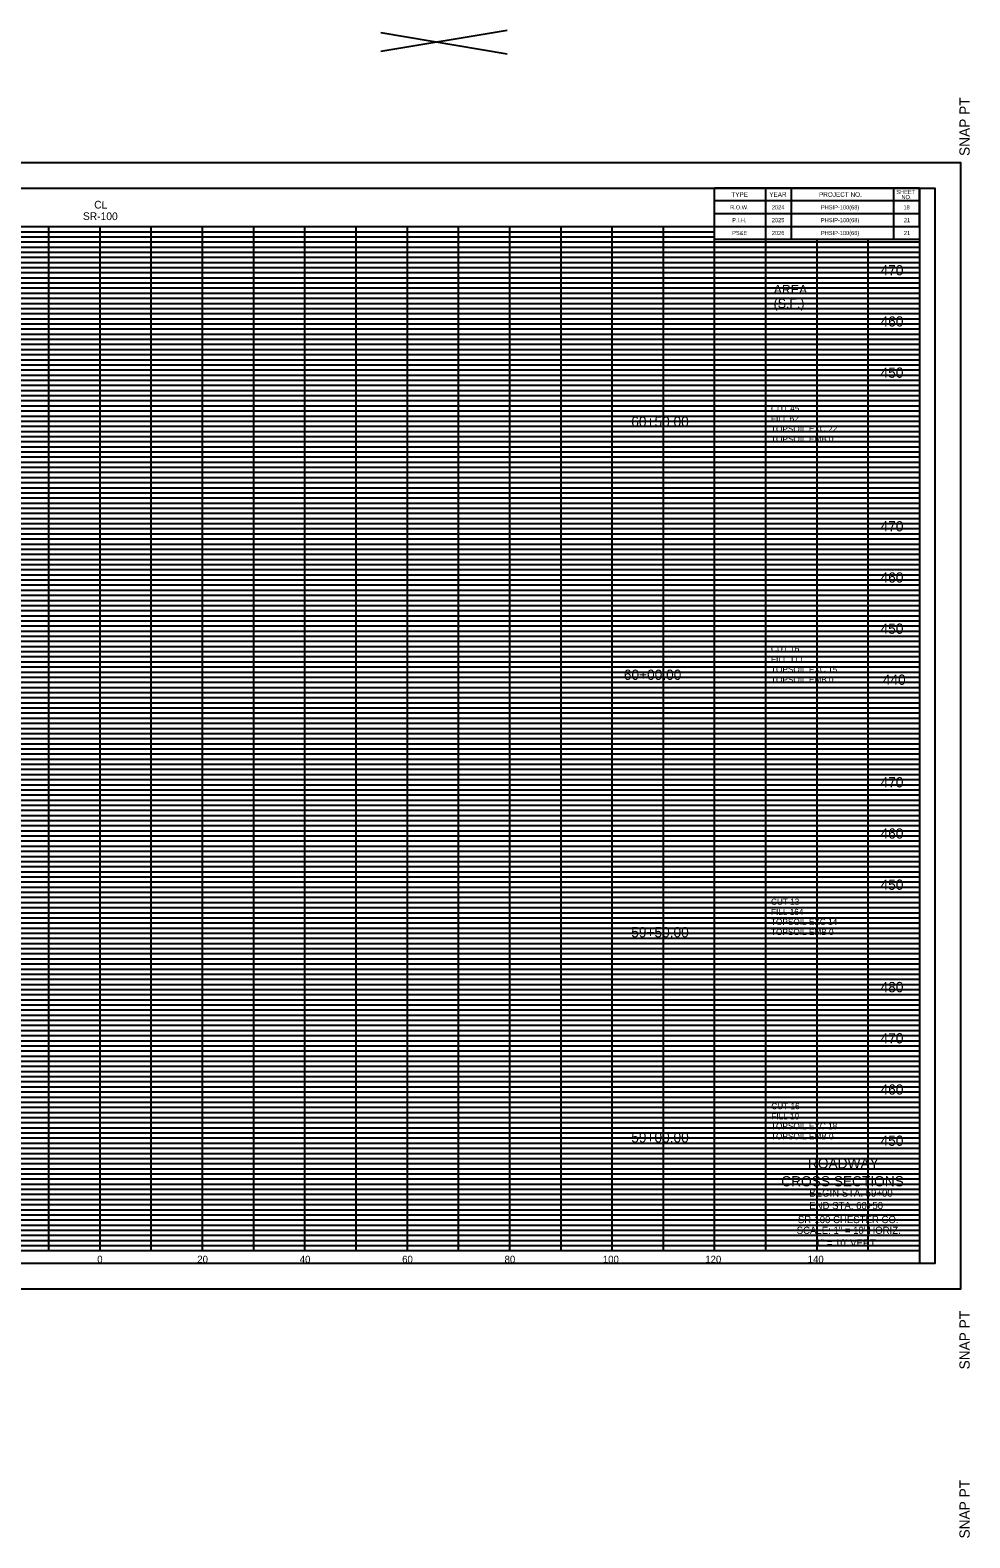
# Model space of a CAD drawing. Extents: x 37 to 1710, y 707 to 2305.
# Drawn here: x 1146.3 to 1329.8, y 1213.9 to 1508.4 of the extents above; entities that cross this region are included whole.
import ezdxf

# ---------------------------------------------------------------- set-up
doc = ezdxf.new("R2010")
doc.units = 0
for name, color, linetype in [('DESIGN - DRAINAGE - Special Ditch Width Text', 7, 'Continuous'), ('DESIGN - SCRATCH - User 1', 7, 'Continuous'), ('DESIGN - SHEET - Corner Text', 7, 'Continuous'), ('DESIGN - SHEET - Light Grid', 7, 'Continuous'), ('DESIGN - SHEET - Linework', 7, 'Continuous'), ('DESIGN - SHEET - Plot Shape', 7, 'Continuous'), ('DESIGN - TYPICAL - Text', 7, 'Continuous')]:
    doc.layers.add(name, color=color, linetype=linetype)

msp = doc.modelspace()

# ---------------------------------------------------------------- linework, layer by layer
at = {"layer": 'DESIGN - SCRATCH - User 1'}
for p, q in [((1214.81, 1504.24), (1239.5, 1508.36)), ((1214.81, 1507.87), (1239.5, 1503.75)), ((1285, 1473.75), (1285, 1473.75)), ((1292.5, 1473.75), (1292.5, 1473.75)), ((1305, 1473.75), (1305, 1473.75)), ((1317.5, 1473.75), (1317.5, 1473.75)), ((1285, 1471.25), (1285, 1471.25)), ((1292.5, 1471.25), (1292.5, 1471.25)), ((1305, 1471.25), (1305, 1471.25)), ((1317.5, 1471.25), (1317.5, 1471.25))]:
    msp.add_line(p, q, dxfattribs=at)
at = {"layer": 'DESIGN - SHEET - Light Grid'}
for p, q in [((1000, 1469), (1280, 1469)), ((1000, 1468), (1280, 1468)), ((1000, 1467), (1320, 1467)), ((1000, 1466), (1320, 1466)), ((1000, 1465), (1320, 1465)), ((1000, 1464), (1320, 1464)), ((1000, 1463), (1320, 1463)), ((1000, 1462), (1320, 1462)), ((1000, 1461), (1320, 1461)), ((1000, 1459), (1320, 1459)), ((1000, 1458), (1320, 1458)), ((1000, 1457), (1320, 1457)), ((1000, 1456), (1320, 1456)), ((1000, 1455), (1320, 1455)), ((1000, 1454), (1320, 1454)), ((1000, 1453), (1320, 1453)), ((1000, 1452), (1320, 1452)), ((1000, 1451), (1320, 1451)), ((1000, 1449), (1320, 1449)), ((1000, 1448), (1320, 1448)), ((1000, 1447), (1320, 1447)), ((1000, 1446), (1320, 1446)), ((1000, 1445), (1320, 1445)), ((1000, 1444), (1320, 1444)), ((1000, 1443), (1320, 1443)), ((1000, 1442), (1320, 1442)), ((1000, 1441), (1320, 1441)), ((1000, 1439), (1320, 1439)), ((1000, 1438), (1320, 1438)), ((1000, 1437), (1320, 1437)), ((1000, 1436), (1320, 1436)), ((1000, 1435), (1320, 1435)), ((1000, 1434), (1320, 1434)), ((1000, 1433), (1320, 1433)), ((1000, 1432), (1320, 1432)), ((1000, 1431), (1320, 1431)), ((1000, 1429), (1320, 1429)), ((1000, 1428), (1320, 1428)), ((1000, 1427), (1320, 1427)), ((1000, 1426), (1320, 1426)), ((1000, 1425), (1320, 1425)), ((1000, 1424), (1320, 1424)), ((1000, 1423), (1320, 1423)), ((1000, 1422), (1320, 1422)), ((1000, 1421), (1320, 1421)), ((1000, 1419), (1320, 1419)), ((1000, 1418), (1320, 1418)), ((1000, 1417), (1320, 1417)), ((1000, 1416), (1320, 1416)), ((1000, 1415), (1320, 1415)), ((1000, 1414), (1320, 1414)), ((1000, 1413), (1320, 1413)), ((1000, 1412), (1320, 1412)), ((1000, 1411), (1320, 1411)), ((1000, 1409), (1320, 1409)), ((1000, 1408), (1320, 1408)), ((1000, 1407), (1320, 1407)), ((1000, 1406), (1320, 1406)), ((1000, 1405), (1320, 1405)), ((1000, 1404), (1320, 1404)), ((1000, 1403), (1320, 1403)), ((1000, 1402), (1320, 1402)), ((1000, 1401), (1320, 1401)), ((1000, 1399), (1320, 1399)), ((1000, 1398), (1320, 1398)), ((1000, 1397), (1320, 1397)), ((1000, 1396), (1320, 1396)), ((1000, 1395), (1320, 1395)), ((1000, 1394), (1320, 1394)), ((1000, 1393), (1320, 1393)), ((1000, 1392), (1320, 1392)), ((1000, 1391), (1320, 1391)), ((1000, 1389), (1320, 1389)), ((1000, 1388), (1320, 1388)), ((1000, 1387), (1320, 1387)), ((1000, 1386), (1320, 1386)), ((1000, 1385), (1320, 1385)), ((1000, 1384), (1320, 1384)), ((1000, 1383), (1320, 1383)), ((1000, 1382), (1320, 1382)), ((1000, 1381), (1320, 1381)), ((1000, 1379), (1320, 1379)), ((1000, 1378), (1320, 1378)), ((1000, 1377), (1320, 1377)), ((1000, 1376), (1320, 1376)), ((1000, 1375), (1320, 1375)), ((1000, 1374), (1320, 1374)), ((1000, 1373), (1320, 1373)), ((1000, 1372), (1320, 1372)), ((1000, 1371), (1320, 1371)), ((1000, 1369), (1320, 1369)), ((1000, 1368), (1320, 1368)), ((1000, 1367), (1320, 1367)), ((1000, 1366), (1320, 1366)), ((1000, 1365), (1320, 1365)), ((1000, 1364), (1320, 1364)), ((1000, 1363), (1320, 1363)), ((1000, 1362), (1320, 1362)), ((1000, 1361), (1320, 1361)), ((1000, 1359), (1320, 1359)), ((1000, 1358), (1320, 1358)), ((1000, 1357), (1320, 1357)), ((1000, 1356), (1320, 1356)), ((1000, 1355), (1320, 1355)), ((1000, 1354), (1320, 1354)), ((1000, 1353), (1320, 1353)), ((1000, 1352), (1320, 1352)), ((1000, 1351), (1320, 1351)), ((1000, 1349), (1320, 1349)), ((1000, 1348), (1320, 1348)), ((1000, 1347), (1320, 1347)), ((1000, 1346), (1320, 1346)), ((1000, 1345), (1320, 1345)), ((1000, 1344), (1320, 1344)), ((1000, 1343), (1320, 1343)), ((1000, 1342), (1320, 1342)), ((1000, 1341), (1320, 1341)), ((1000, 1339), (1320, 1339)), ((1000, 1338), (1320, 1338)), ((1000, 1337), (1320, 1337)), ((1000, 1336), (1320, 1336)), ((1000, 1335), (1320, 1335)), ((1000, 1334), (1320, 1334)), ((1000, 1333), (1320, 1333)), ((1000, 1332), (1320, 1332)), ((1000, 1331), (1320, 1331)), ((1000, 1329), (1320, 1329)), ((1000, 1328), (1320, 1328)), ((1000, 1327), (1320, 1327)), ((1000, 1326), (1320, 1326)), ((1000, 1325), (1320, 1325)), ((1000, 1324), (1320, 1324)), ((1000, 1323), (1320, 1323)), ((1000, 1322), (1320, 1322)), ((1000, 1321), (1320, 1321)), ((1000, 1319), (1320, 1319)), ((1000, 1318), (1320, 1318)), ((1000, 1317), (1320, 1317)), ((1000, 1316), (1320, 1316)), ((1000, 1315), (1320, 1315)), ((1000, 1314), (1320, 1314)), ((1000, 1313), (1320, 1313)), ((1000, 1312), (1320, 1312)), ((1000, 1311), (1320, 1311)), ((1000, 1309), (1320, 1309)), ((1000, 1308), (1320, 1308)), ((1000, 1307), (1320, 1307)), ((1000, 1306), (1320, 1306)), ((1000, 1305), (1320, 1305)), ((1000, 1304), (1320, 1304)), ((1000, 1303), (1320, 1303)), ((1000, 1302), (1320, 1302)), ((1000, 1301), (1320, 1301)), ((1000, 1299), (1320, 1299)), ((1000, 1298), (1320, 1298)), ((1000, 1297), (1320, 1297)), ((1000, 1296), (1320, 1296)), ((1000, 1295), (1320, 1295)), ((1000, 1294), (1320, 1294)), ((1000, 1293), (1320, 1293)), ((1000, 1292), (1320, 1292)), ((1000, 1291), (1320, 1291)), ((1000, 1289), (1320, 1289)), ((1000, 1288), (1320, 1288)), ((1000, 1287), (1320, 1287)), ((1000, 1286), (1320, 1286)), ((1000, 1285), (1320, 1285)), ((1000, 1284), (1320, 1284)), ((1000, 1283), (1320, 1283)), ((1000, 1282), (1320, 1282)), ((1000, 1281), (1320, 1281)), ((1000, 1279), (1320, 1279)), ((1000, 1278), (1320, 1278)), ((1000, 1277), (1320, 1277)), ((1000, 1276), (1320, 1276)), ((1000, 1275), (1320, 1275)), ((1000, 1274), (1320, 1274)), ((1000, 1273), (1320, 1273)), ((1000, 1272), (1320, 1272)), ((1000, 1271), (1320, 1271))]:
    msp.add_line(p, q, dxfattribs=at)
at = {"layer": 'DESIGN - SHEET - Linework'}
for p, q in [((1320, 1477.5), (1280, 1477.5)), ((1280, 1470), (1280, 1477.5)), ((1290, 1470), (1290, 1477.5)), ((1295, 1467.5), (1295, 1477.5)), ((1315, 1467.5), (1315, 1477.5)), ((1320, 1470), (1320, 1477.5)), ((1320, 1475), (1280, 1475)), ((1320, 1472.5), (1280, 1472.5)), ((1000, 1470), (1320, 1470)), ((1150, 1270), (1150, 1470)), ((1160, 1270), (1160, 1470)), ((1170, 1270), (1170, 1470)), ((1180, 1270), (1180, 1470)), ((1190, 1270), (1190, 1470)), ((1200, 1270), (1200, 1470)), ((1210, 1270), (1210, 1470)), ((1220, 1270), (1220, 1470)), ((1230, 1270), (1230, 1470)), ((1240, 1270), (1240, 1470)), ((1250, 1270), (1250, 1470)), ((1260, 1270), (1260, 1470)), ((1270, 1270), (1270, 1470)), ((1280, 1270), (1280, 1470)), ((1290, 1270), (1290, 1470)), ((1320, 1467.5), (1280, 1467.5)), ((1300, 1270), (1300, 1467.5)), ((1310, 1270), (1310, 1467.5)), ((1000, 1460), (1320, 1460)), ((1000, 1450), (1320, 1450)), ((1000, 1440), (1320, 1440)), ((1000, 1430), (1320, 1430)), ((1000, 1420), (1320, 1420)), ((1000, 1410), (1320, 1410)), ((1000, 1400), (1320, 1400)), ((1000, 1390), (1320, 1390)), ((1000, 1380), (1320, 1380)), ((1000, 1370), (1320, 1370)), ((1000, 1360), (1320, 1360)), ((1000, 1350), (1320, 1350)), ((1000, 1340), (1320, 1340)), ((1000, 1330), (1320, 1330)), ((1000, 1320), (1320, 1320)), ((1000, 1310), (1320, 1310)), ((1000, 1300), (1320, 1300)), ((1000, 1290), (1320, 1290)), ((1000, 1280), (1320, 1280)), ((1000, 1270), (1320, 1270))]:
    msp.add_line(p, q, dxfattribs=at)
for points in [[(988, 1482.5), (1328, 1482.5), (1328, 1262.5), (988, 1262.5)], [(1000, 1477.5), (1320, 1477.5), (1320, 1267.5), (1000, 1267.5)]]:
    msp.add_lwpolyline(points, close=True, dxfattribs=at)
at = {"layer": 'DESIGN - SHEET - Plot Shape'}
msp.add_lwpolyline([(993, 1477.5), (1323, 1477.5), (1323, 1267.5), (993, 1267.5)], close=True, dxfattribs=at)

# ---------------------------------------------------------------- texts
at = {"layer": 'DESIGN - DRAINAGE - Special Ditch Width Text'}
for s, p in [('SR-100', (1156.64, 1471.29)), ('CL', (1158.85, 1473.53))]:
    msp.add_text(s, height=1.5, rotation=359.6675, dxfattribs=at).set_placement(p)
at = {"layer": 'DESIGN - SHEET - Corner Text'}
for s, p in [('  SNAP PT', (1329.8, 1482.3)), ('SNAP PT  ', (1329.8, 1246.8)), ('  SNAP PT', (1329.8, 1212.3))]:
    msp.add_text(s, height=2, rotation=90, dxfattribs=at).set_placement(p)
for s, height, p in [('R.O.W.', 0.8, (1283.02, 1473.35)), ('2024', 0.8, (1291.16, 1473.35)), ('PHSIP-100(68)', 0.8, (1300.75, 1473.35)), ('18', 0.8, (1316.86, 1473.35)), ('P.I.H.', 0.8, (1283.45, 1470.85)), ('2025', 0.8, (1291.16, 1470.85)), ('PHSIP-100(68)', 0.8, (1300.75, 1470.85)), ('21', 0.8, (1316.94, 1470.85)), ('PS&E', 0.8, (1283.42, 1468.35)), ('2026', 0.8, (1291.16, 1468.35)), ('PHSIP-100(68)', 0.8, (1300.75, 1468.35)), ('21', 0.8, (1316.94, 1468.35)), ('ROADWAY ', 2, (1298.23, 1286.05)), ('CROSS SECTIONS', 2, (1293.01, 1282.55)), ('BEGIN STA. 59+00', 1.4, (1298.47, 1280.55)), ('END STA. 60+50', 1.4, (1298.47, 1278.1)), ('SR-100 CHESTER CO.', 1.4, (1296.25, 1275.37)), ('SCALE: 1" = 10\' HORIZ.', 1.4, (1296.02, 1273.26)), ('       1" = 10\' VERT.   ', 1.4, (1296.02, 1270.81))]:
    msp.add_text(s, height=height, dxfattribs=at).set_placement(p)
at = {"layer": 'DESIGN - SHEET - Light Grid'}
for s, height, p in [('TYPE', 0.9, (1283.26, 1475.8)), ('YEAR', 0.9, (1290.66, 1475.8)), ('PROJECT NO.', 0.9, (1300.38, 1475.8)), ('SHEET', 0.8, (1315.47, 1476.35)), ('NO.', 0.8, (1316.47, 1475.35))]:
    msp.add_text(s, height=height, dxfattribs=at).set_placement(p)
at = {"layer": 'DESIGN - TYPICAL - Text'}
for s, height, p in [('     470     ', 2, (1308.68, 1460.47)), ('AREA ', 1.8, (1291.52, 1456.79)), ('(S.F.)', 1.8, (1291.52, 1454.09)), ('     460     ', 2, (1308.68, 1450.47)), ('     450     ', 2, (1308.68, 1440.47)), ('CUT 45', 1.2, (1291, 1433.89)), ('     60+50.00     ', 2, (1260, 1430.89)), ('TOPSOIL EXC 22', 1.2, (1291, 1429.89)), ('FILL 62', 1.2, (1291, 1431.89)), ('TOPSOIL EMB 0', 1.2, (1291, 1427.9)), ('     470     ', 2, (1308.68, 1410.47)), ('     460     ', 2, (1308.68, 1400.47)), ('     450     ', 2, (1308.68, 1390.47)), ('CUT 16', 1.2, (1291, 1386.95)), ('TOPSOIL EXC 15', 1.2, (1291, 1382.91)), ('FILL 111', 1.2, (1291, 1384.95)), ('     60+00.00     ', 2, (1258.55, 1381.47)), ('TOPSOIL EMB 0', 1.2, (1291, 1380.92)), ('440', 2, (1312.84, 1380.5)), ('     470     ', 2, (1308.68, 1360.47)), ('     460     ', 2, (1308.68, 1350.47)), ('     450     ', 2, (1308.68, 1340.47)), ('CUT 13', 1.2, (1291, 1337.55)), ('TOPSOIL EXC 14', 1.2, (1291, 1333.61)), ('FILL 164', 1.2, (1291, 1335.55)), ('     59+50.00     ', 2, (1260, 1331.19)), ('TOPSOIL EMB 0', 1.2, (1291, 1331.63)), ('     480     ', 2, (1308.68, 1320.47)), ('     470     ', 2, (1308.68, 1310.47)), ('     460     ', 2, (1308.68, 1300.47)), ('CUT 16', 1.2, (1291.06, 1297.62)), ('FILL 10', 1.2, (1291.06, 1295.62)), ('     59+00.00     ', 2, (1260, 1291.11)), ('TOPSOIL EXC 18', 1.2, (1291, 1293.72)), ('TOPSOIL EMB 0', 1.2, (1291, 1291.73)), ('     450     ', 2, (1308.68, 1290.47)), ('     0     ', 1.4, (1156.84, 1267.6)), ('     0     ', 1.4, (1156.84, 1267.6)), ('     20     ', 1.4, (1176.38, 1267.6)), ('     40     ', 1.4, (1196.38, 1267.6)), ('     60     ', 1.4, (1216.38, 1267.6)), ('     80     ', 1.4, (1236.38, 1267.6)), ('     100     ', 1.4, (1255.57, 1267.6)), ('     120     ', 1.4, (1275.57, 1267.6)), ('     140     ', 1.4, (1295.57, 1267.6))]:
    msp.add_text(s, height=height, dxfattribs=at).set_placement(p)

doc.saveas('drawing.dxf')
